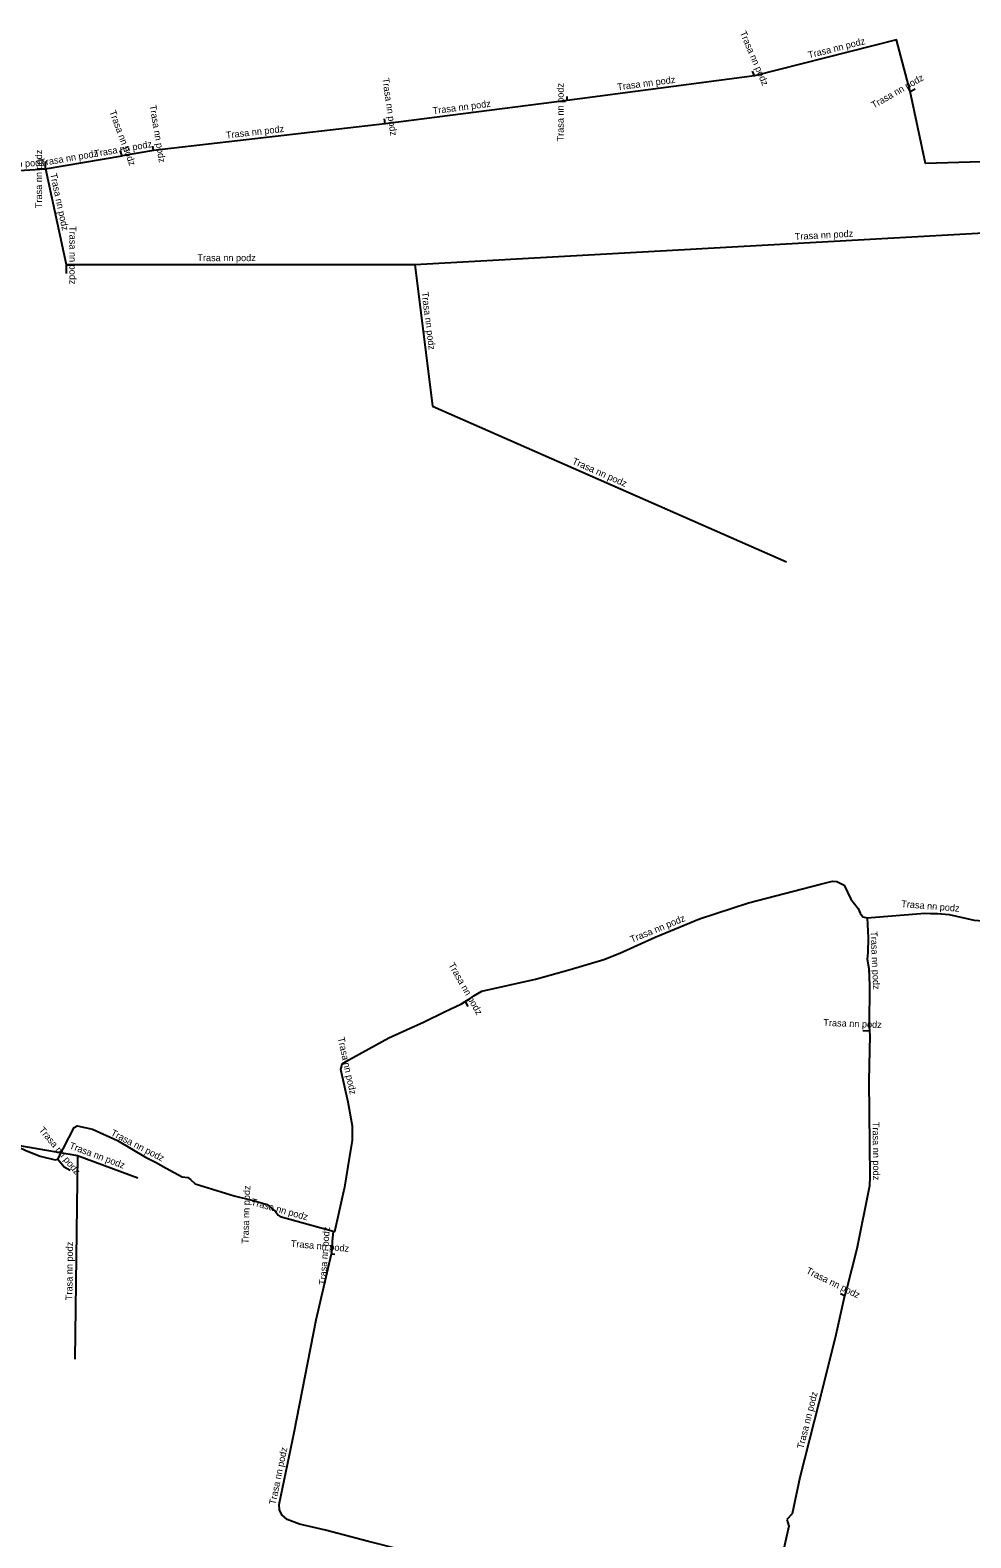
# Model space of a CAD drawing. Extents: x -724876 to -714160, y -1042389 to -1039790.
# Drawn here: x -715399 to -715261.4, y -1040732.1 to -1040511.5 of the extents above; entities that cross this region are included whole.
import ezdxf

# ---------------------------------------------------------------- set-up
doc = ezdxf.new("R2010")
doc.units = 0
doc.layers.add('Level 11', color=7, linetype='Continuous')
doc.layers.add('Level 20', color=7, linetype='Continuous')

msp = doc.modelspace()

# ---------------------------------------------------------------- linework, layer by layer
at = {"layer": 'Level 11'}
for p, q in [((-715293.1, -1040518.2), (-715293.4, -1040517.5)), ((-715293.1, -1040518.2), (-715320.5, -1040521.8)), ((-715270.3, -1040520.5), (-715269.6, -1040520.1)), ((-715320.5, -1040521.8), (-715347.1, -1040525.2)), ((-715320.5, -1040521.8), (-715320.5, -1040521.2)), ((-715347.1, -1040525.2), (-715347.2, -1040524.5)), ((-715347.1, -1040525.2), (-715381, -1040529.1)), ((-715381, -1040529.1), (-715381.1, -1040528.5)), ((-715396.8, -1040531.8), (-715385.6, -1040529.9)), ((-715396.8, -1040531.8), (-715396.8, -1040530.7)), ((-715385.6, -1040529.9), (-715385.9, -1040529.1)), ((-715381, -1040529.1), (-715385.6, -1040529.9)), ((-715401.4, -1040532.1), (-715396.8, -1040531.8)), ((-715396.8, -1040531.8), (-715393.8, -1040545.8)), ((-715393.8, -1040545.8), (-715342.8, -1040545.8)), ((-715393.8, -1040545.8), (-715393.8, -1040547.1)), ((-715342.8, -1040545.8), (-715340.2, -1040566.5)), ((-715340.2, -1040566.5), (-715288.4, -1040589.3)), ((-715335.43, -1040653.6), (-715335.03, -1040654.31)), ((-715276.29, -1040657.92), (-715277.27, -1040657.88)), ((-715414.6, -1040672.3), (-715392.1, -1040676.1)), ((-715392.1, -1040676.1), (-715392.5, -1040705.9)), ((-715392.1, -1040676.1), (-715383.3, -1040679.4)), ((-715366.41, -1040682.68), (-715366.42, -1040682.91)), ((-715354.98, -1040690.51), (-715354.48, -1040690.55)), ((-715279.95, -1040696.65), (-715280.49, -1040696.38))]:
    msp.add_line(p, q, dxfattribs=at)
for points in [[(-715270.3, -1040520.5), (-715272.3, -1040512.9), (-715293.1, -1040518.2)], [(-715228.14, -1040528.36), (-715233.8, -1040530), (-715268.1, -1040531), (-715270.3, -1040520.5)], [(-715342.8, -1040545.8), (-715235, -1040539.8), (-715222.41, -1040529.76)], [(-715335.43, -1040653.6), (-715334.66, -1040653.14), (-715334.15, -1040652.78), (-715332.99, -1040652.08), (-715325.12, -1040650.34), (-715320.05, -1040648.92), (-715315.11, -1040647.47), (-715312.77, -1040646.53), (-715307.64, -1040644.17), (-715301.12, -1040641.5), (-715293.95, -1040639.18), (-715283.44, -1040636.42), (-715281.68, -1040636.01), (-715281.03, -1040636.04), (-715280, -1040636.57), (-715279, -1040638.62), (-715277.95, -1040640.01), (-715277.62, -1040640.69), (-715277.26, -1040641.2), (-715276.59, -1040641.38)], [(-715276.59, -1040641.38), (-715276.47, -1040644.26), (-715276.54, -1040646.42), (-715276.63, -1040647.38), (-715276.38, -1040648.76), (-715276.27, -1040651.27), (-715276.3, -1040657.18), (-715276.29, -1040657.92)], [(-715276.59, -1040641.38), (-715268.17, -1040640.67), (-715267.33, -1040640.7), (-715266.33, -1040640.71), (-715264.61, -1040640.85), (-715260.97, -1040641.71), (-715255.04, -1040642.16), (-715254.45, -1040641.83)], [(-715354.7, -1040687.2), (-715354.47, -1040687.26), (-715353.86, -1040684.41), (-715353.14, -1040681.35), (-715353, -1040680.76), (-715352.54, -1040677.73), (-715351.9, -1040673.86), (-715351.92, -1040671.84), (-715352.55, -1040668.3), (-715353.58, -1040663.54), (-715353.43, -1040662.7), (-715352.42, -1040662.14), (-715346.59, -1040658.91), (-715341.43, -1040656.59), (-715338.43, -1040655.13), (-715335.94, -1040653.92), (-715335.43, -1040653.6)], [(-715276.29, -1040657.92), (-715276.23, -1040658.56), (-715276.37, -1040665.14), (-715276.24, -1040679.26), (-715276.28, -1040680.55), (-715278.13, -1040689.76), (-715279.58, -1040695.55), (-715279.95, -1040696.65)], [(-715415.05, -1040670.77), (-715412.18, -1040671.36), (-715408.67, -1040672.18), (-715406.27, -1040672.84), (-715403.83, -1040673.44), (-715399.67, -1040675.38), (-715397.6, -1040676.24), (-715395.38, -1040676.74), (-715394.98, -1040676.65)], [(-715394.98, -1040676.65), (-715392.6, -1040672.03), (-715392.16, -1040671.77), (-715389.91, -1040672.29), (-715386.28, -1040673.93), (-715382.18, -1040676.35), (-715380.72, -1040677.1), (-715379.15, -1040677.96), (-715376.79, -1040679.24), (-715375.96, -1040679.35), (-715375.58, -1040679.64), (-715374.92, -1040680.29), (-715369.19, -1040682.02), (-715366.41, -1040682.68)], [(-715394.98, -1040676.65), (-715394.05, -1040677.77), (-715393.21, -1040678.26)], [(-715366.41, -1040682.68), (-715364.39, -1040683.29), (-715363.21, -1040684.26), (-715362.78, -1040684.86), (-715362.5, -1040685.04), (-715354.7, -1040687.2)], [(-715354.7, -1040687.2), (-715354.85, -1040688.69), (-715354.98, -1040690.51)], [(-715339.53, -1040735.1), (-715349.54, -1040732.57), (-715355.85, -1040730.92), (-715359.65, -1040730.03), (-715361.43, -1040729.36), (-715362.22, -1040728.69), (-715362.57, -1040727.95), (-715362.62, -1040727.18), (-715360.42, -1040716.62), (-715357.2, -1040700.15), (-715354.98, -1040690.51)], [(-715279.95, -1040696.65), (-715281.31, -1040702.8), (-715283.7, -1040712.3), (-715286.47, -1040723.24), (-715287.6, -1040728.55), (-715288.34, -1040729.35)], [(-715288.34, -1040729.35), (-715288.09, -1040730.34), (-715290.77, -1040742.27), (-715291.43, -1040744.35), (-715292.5, -1040745.63), (-715293.26, -1040745.95), (-715294.09, -1040746.05), (-715296.01, -1040745.6)]]:
    msp.add_lwpolyline(points, dxfattribs=at)

# ---------------------------------------------------------------- texts
at = {"layer": 'Level 20'}
for rotation, p in [(293.1986, (-715295.27, -1040511.87)), (14.2952, (-715285.11, -1040515.65)), (278.1301, (-715347.54, -1040518.56)), (90, (-715321, -1040527.79)), (7.485, (-715313.1, -1040520.32)), (29.7449, (-715275.66, -1040522.99)), (7.284, (-715340.1, -1040523.8)), (290.556, (-715387.49, -1040523.44)), (279.4623, (-715381.59, -1040522.52)), (6.5627, (-715370.35, -1040527.37)), (9.8658, (-715389.58, -1040530.08)), (3.7314, (-715405.41, -1040531.86)), (90, (-715397.3, -1040537.54)), (9.6282, (-715397.48, -1040531.41)), (282.0948, (-715396.13, -1040532.55)), (270, (-715393.3, -1040540.16)), (3.1857, (-715287.16, -1040542.2)), (277.1591, (-715341.79, -1040549.85)), (336.2431, (-715319.85, -1040574.91)), (355.3663, (-715271.66, -1040639.78)), (22.2699, (-715311.04, -1040645.02)), (272.559, (-715276.12, -1040643.33)), (299.5878, (-715337.9, -1040648.24)), (357.7862, (-715283.04, -1040657.16)), (282.1744, (-715354.06, -1040658.92)), (309.6996, (-715397.84, -1040672.43)), (332.7963, (-715387.35, -1040673.13)), (270.5516, (-715275.82, -1040671.2)), (339.444, (-715393.41, -1040675.07)), (88.218, (-715367.11, -1040689.06)), (344.5531, (-715366.8, -1040683.34)), (85.8898, (-715355.81, -1040695.09)), (89.231, (-715392.88, -1040697.28)), (354.9909, (-715360.95, -1040689.48)), (333.8609, (-715285.64, -1040693.3)), (75.805, (-715285.94, -1040719.1)), (78.243, (-715363.15, -1040727.27))]:
    msp.add_text('Trasa nn podz', height=1, rotation=rotation, dxfattribs=at).set_placement(p)
msp.add_text('Trasa nn podz', height=1, dxfattribs=at).set_placement((-715374.59, -1040545.3))

doc.saveas('drawing.dxf')
